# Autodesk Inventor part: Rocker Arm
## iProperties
Created: 2005-03
Part Number: Rocker Arm
Document SubType Name: Modeling
Designer: brent
Material: Steel, Mild
Density: 7.86 g/cm^3
Author: Autodesk Inc.
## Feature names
1. Extrusion1
2. Extrusion3
3. Fillet2
4. Hole1
5. Bearing Countersink [Hole]
6. Mirror2
7. Hole2
8. Fillet4
9. Fillet8
10. ExteriorFillets [Fillet]
